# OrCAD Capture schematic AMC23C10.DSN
size A
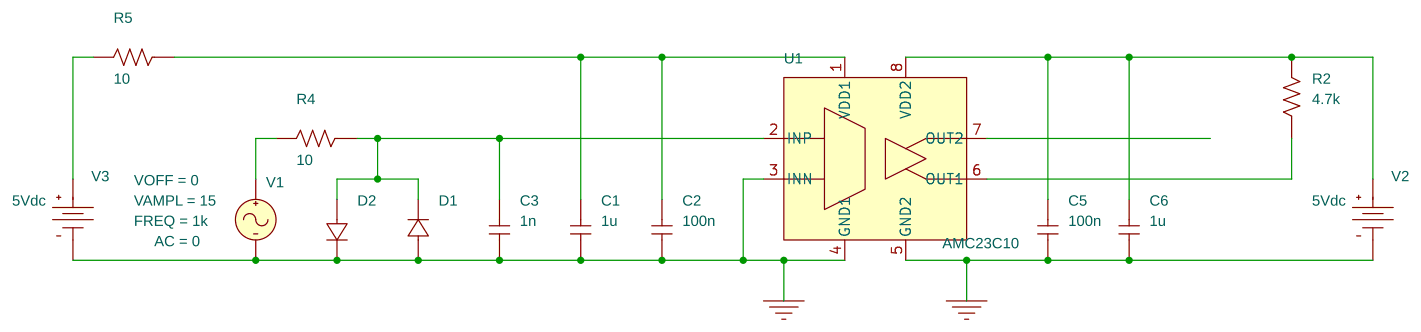
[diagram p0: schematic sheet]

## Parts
C1  1u  [cap196]
C2  100n  [cap196]
C3  1n  [cap196]
C5  100n  [cap196]
C6  1u  [cap196]
D1  Dbreak
D2  Dbreak
R2  4.7k  [AXRC05]
R4  10  [AXRC05]
R5  10  [AXRC05]
U1  AMC23C10
V1  VSIN
V2  VDC
V3  VDC

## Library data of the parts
C1-C3 C5 C6 = C
D1 D2 = Dbreak
R2 R4 R5 = R
U1 = AMC23C10
V1 = VSIN: AC: 0; FREQ: 1k; VAMPL: 15; VOFF: 0
V2 V3 = VDC: DC: 5Vdc

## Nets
0: C1.1 C2.1 C3.1 C5.1 C6.1 D1.0(1) D2.1(2) U1.3(INN) U1.4(GND1) U1.5(GND2) V1.2(-) V2.1(-) V3.1(-)
N23406: R4.2 V1.1(+)
N23450: C1.2 C2.2 R5.1 U1.1(VDD1)
N23454: C5.2 C6.2 R2.2 U1.8(VDD2) V2.0(+)
N23638: R2.1 U1.6(OUT1)
N23674: C3.2 D1.1(2) D2.0(1) R4.1 U1.2(INP)
N25400: R5.2 V3.0(+)

Not connected (* = marked no-connect by the designer): U1 7(OUT2)
